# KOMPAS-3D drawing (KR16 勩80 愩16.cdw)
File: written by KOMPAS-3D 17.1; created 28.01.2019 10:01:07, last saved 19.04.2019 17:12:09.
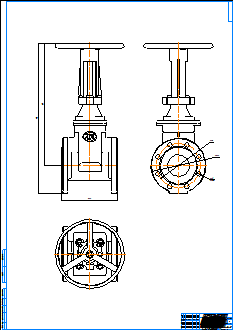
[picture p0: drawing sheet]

Sheet 1: A0, portrait

Title block, sheet 1: name: KR16 Ду80 Ру16; material: Внимание! Данный продукт является объектом авторского права ООО «Торговый Дом АДЛ». / Запрещается изменение, копирование, распространение / (в том числе путем копирования на другие сайты и ресурсы в Интернете) / или любое иное использование информации и объектов без предварительного / согласия правообладателя (ООО «Торговый Дом АДЛ»).; sheets: 1; organisation: ООО "Торговый дом АДЛ"; sheet format: A0; stored path: \\adlc.lan\data\АДЛ_ПКД\3D-модели\ADL production\Клиновые задвижки серии KR ГРАНАР\Клиновые задвижки KR16\Со штурвалом\KOMPAS 2D\KR16 Ду80.cdw

Views: Вид 1
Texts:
  user
Dimensions and other numbers on the sheet: 441; 541; 203; 1:1; 1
